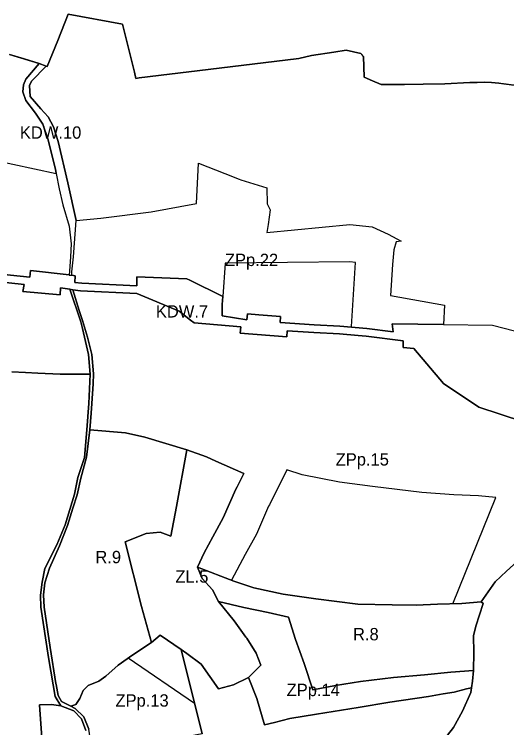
# Model space of a CAD drawing. Extents: x 7418114 to 7422197, y 5546299 to 5548348.
# Drawn here: x 7419820 to 7420219, y 5547025 to 5547603 of the extents above; entities that cross this region are included whole.
import ezdxf

# ---------------------------------------------------------------- set-up
doc = ezdxf.new("R2010")
doc.units = 0
for name, color, linetype in [('_STRZELNICA_SIKORNIK', 7, 'Continuous'), ('linie_lokalizacyjne', 7, 'Continuous'), ('linie_rozgraniczajace', 7, 'Continuous'), ('oznaczenia_przeznaczen', 7, 'Continuous')]:
    doc.layers.add(name, color=color, linetype=linetype)

msp = doc.modelspace()

# ---------------------------------------------------------------- linework, layer by layer
at = {"layer": '_STRZELNICA_SIKORNIK'}
msp.add_lwpolyline([(7419816.43, 5547570.76), (7419840.61, 5547563.53), (7419846.25, 5547561.23), (7419847.04, 5547560.97), (7419855.58, 5547582.15), (7419864.12, 5547603.34), (7419908.13, 5547595.43), (7419917.74, 5547556.32), (7419919, 5547551.22), (7419921.65, 5547551.82), (7419986.34, 5547559.67), (7420051.04, 5547567.5), (7420061.08, 5547569.85), (7420079.37, 5547572.65), (7420089.14, 5547574.3), (7420101.06, 5547571.55), (7420103.3, 5547569.25), (7420103.75, 5547552.48), (7420110.66, 5547549.52), (7420117.58, 5547546.55), (7420136.39, 5547546.49), (7420151.56, 5547546.66), (7420169.15, 5547546.87), (7420189.5, 5547547.96), (7420195.24, 5547548.2), (7420200.99, 5547548.43), (7420206.94, 5547547.99), (7420212.89, 5547547.55), (7420244.04, 5547543.38)], dxfattribs=at)
at = {"layer": 'linie_lokalizacyjne'}
for points in [[(7420093.68, 5547350.47), (7420096.72, 5547402.35), (7420092.13, 5547402.79), (7419991.18, 5547401.81), (7419989.24, 5547374.67)], [(7420041.28, 5547234.25), (7420027.07, 5547205.92), (7420026.39, 5547204.82), (7420016.55, 5547182.22), (7420007.52, 5547165.77), (7419996.33, 5547145)], [(7420210.53, 5547211.94), (7420196.36, 5547213.25), (7420176.4, 5547214.18), (7420150.42, 5547216.04), (7420110.67, 5547220.76), (7420083.74, 5547224.37), (7420053.75, 5547230.19), (7420041.28, 5547234.25)], [(7420175.57, 5547125.84), (7420210.53, 5547211.94)], [(7419966.43, 5547045.05), (7419912.67, 5547081.91)]]:
    msp.add_lwpolyline(points, dxfattribs=at)
at = {"layer": 'linie_rozgraniczajace'}
for p, q in [((7419829.88, 5547550.8), (7419840.61, 5547563.53)), ((7419846.25, 5547561.23), (7419834.32, 5547549.06)), ((7419846.25, 5547561.23), (7419840.61, 5547563.53)), ((7419834.32, 5547549.06), (7419832.71, 5547545.52)), ((7419833.34, 5547536.82), (7419832.71, 5547545.52)), ((7419832.71, 5547545.52), (7419833.34, 5547536.82)), ((7420189.5, 5547547.97), (7420169.16, 5547546.87)), ((7419829.88, 5547533.56), (7419837.5, 5547523.32)), ((7419837.5, 5547523.32), (7419843.5, 5547514.44)), ((7419843.5, 5547514.44), (7419837.5, 5547523.32)), ((7419852.27, 5547512.04), (7419847.76, 5547520.37)), ((7419847.76, 5547520.37), (7419852.27, 5547512.04)), ((7419843.5, 5547514.44), (7419847.48, 5547502.44)), ((7419852.27, 5547512.04), (7419855.88, 5547500.36)), ((7419847.48, 5547502.44), (7419853.74, 5547477.81)), ((7419853.74, 5547477.81), (7419854.38, 5547474.48)), ((7420025.11, 5547462.85), (7420025.2, 5547449.89)), ((7419931.39, 5547443.3), (7419967.97, 5547450.04)), ((7419890.59, 5547438.1), (7419931.39, 5547443.3)), ((7420123.3, 5547425.21), (7420133.69, 5547419.69)), ((7419866.94, 5547394.67), (7419868.47, 5547406.76)), ((7419867.06, 5547391.89), (7419866.94, 5547394.67)), ((7419864.92, 5547392.17), (7419867.06, 5547391.89)), ((7420168.02, 5547352.05), (7420207.92, 5547351.59)), ((7420207.92, 5547351.59), (7420225.74, 5547346.86))]:
    msp.add_line(p, q, dxfattribs=at)
for points in [[(7420101.06, 5547571.55), (7420089.14, 5547574.31), (7420079.37, 5547572.65), (7420061.08, 5547569.85), (7420051.04, 5547567.5), (7419986.34, 5547559.67), (7419921.65, 5547551.82), (7419919, 5547551.22), (7419917.74, 5547556.32), (7419908.13, 5547595.43), (7419864.12, 5547603.34), (7419855.58, 5547582.15), (7419847.04, 5547560.97), (7419846.25, 5547561.23)], [(7419840.61, 5547563.53), (7419828.52, 5547567.15), (7419816.43, 5547570.76)], [(7420101.94, 5547570.64), (7420101.94, 5547570.64), (7420101.06, 5547571.55)], [(7420169.16, 5547546.87), (7420151.56, 5547546.66), (7420136.4, 5547546.49), (7420117.58, 5547546.55), (7420110.66, 5547549.52), (7420103.75, 5547552.48), (7420103.3, 5547569.25), (7420101.94, 5547570.64)], [(7419840.61, 5547563.53), (7419829.88, 5547550.8), (7419827.94, 5547546.18)], [(7419832.71, 5547545.52), (7419834.32, 5547549.06), (7419846.25, 5547561.23)], [(7419837.5, 5547523.32), (7419829.88, 5547533.56), (7419827.33, 5547540.52), (7419827.94, 5547546.18), (7419829.88, 5547550.8)], [(7419827.94, 5547546.18), (7419827.33, 5547540.52), (7419829.88, 5547533.56)], [(7420200.99, 5547548.43), (7420195.24, 5547548.2), (7420189.5, 5547547.97)], [(7420212.89, 5547547.55), (7420206.94, 5547547.99), (7420200.99, 5547548.43)], [(7420244.05, 5547543.38), (7420214.57, 5547547.32), (7420212.89, 5547547.55)], [(7419847.76, 5547520.37), (7419842.02, 5547526.73), (7419833.34, 5547536.82)], [(7419833.34, 5547536.82), (7419842.02, 5547526.73), (7419847.76, 5547520.37)], [(7419854.38, 5547474.48), (7419853.74, 5547477.81), (7419847.48, 5547502.44), (7419843.5, 5547514.44)], [(7419868.47, 5547406.76), (7419870.45, 5547436.17), (7419863.69, 5547466.71), (7419855.88, 5547500.36), (7419852.27, 5547512.04)], [(7419855.88, 5547500.36), (7419863.69, 5547466.71), (7419870.45, 5547436.17), (7419890.59, 5547438.1)], [(7419764.68, 5547480.7), (7419775.06, 5547482.43), (7419785.43, 5547484.16), (7419788.3, 5547482.39), (7419801.45, 5547485.6), (7419854.38, 5547474.48)], [(7419801.45, 5547485.6), (7419854.38, 5547474.48), (7419856.82, 5547461.91), (7419859.76, 5547448.87), (7419864.95, 5547431.58), (7419866.38, 5547417.51), (7419866, 5547406.89), (7419865.05, 5547395.37), (7419864.92, 5547392.17), (7419833.44, 5547395.81), (7419833.13, 5547390.31), (7419804.16, 5547393.43)], [(7419967.97, 5547450.04), (7419969.71, 5547482.67), (7419991.02, 5547474.3), (7420002.49, 5547469.91)], [(7419854.38, 5547474.48), (7419856.82, 5547461.91), (7419859.76, 5547448.87)], [(7420002.49, 5547469.91), (7420004.02, 5547469.3), (7420025.11, 5547462.85)], [(7419859.76, 5547448.87), (7419864.95, 5547431.58), (7419866.38, 5547417.51), (7419866, 5547406.89), (7419865.05, 5547395.37), (7419864.92, 5547392.17)], [(7420025.2, 5547449.89), (7420027.76, 5547444.91), (7420026.1, 5547433.19)], [(7420026.1, 5547433.19), (7420025.03, 5547426.47), (7420092.12, 5547432.93), (7420110.44, 5547431.18), (7420123.3, 5547425.21)], [(7420133.69, 5547419.69), (7420129.72, 5547418.91), (7420127.9, 5547412.57)], [(7420127.9, 5547412.57), (7420126.67, 5547400.63), (7420125.2, 5547375.43), (7420168.82, 5547367.82), (7420168.02, 5547352.05)], [(7419804.16, 5547393.43), (7419833.13, 5547390.31), (7419833.44, 5547395.81), (7419864.92, 5547392.17), (7419864.92, 5547392.11), (7419867.06, 5547391.89), (7419869.85, 5547391.51), (7419869.47, 5547386.04), (7419875.1, 5547385.46), (7419919.77, 5547383.47), (7419919.81, 5547390.72), (7419960.25, 5547389.07), (7419962.56, 5547387.92), (7419989.24, 5547374.67), (7419988.86, 5547368.37), (7419988.94, 5547359.04), (7420008.89, 5547355.95), (7420009.25, 5547360.79), (7420018.57, 5547359.98), (7420035.97, 5547358.45), (7420035.69, 5547353.67), (7420063.33, 5547351.77), (7420084.14, 5547350.79), (7420105.98, 5547348.8), (7420127.27, 5547346.04), (7420126.5, 5547352.48), (7420168.01, 5547352.05), (7420168.02, 5547352.05), (7420207.92, 5547351.59), (7420225.74, 5547346.86)], [(7419803.23, 5547387.27), (7419828.31, 5547384.49), (7419827.49, 5547378.8), (7419857.49, 5547375.99), (7419857.92, 5547381.74), (7419865.45, 5547380.62), (7419874.41, 5547354.15), (7419875.64, 5547348.78), (7419880.59, 5547327.87), (7419881.8, 5547311.97), (7419857.71, 5547311.93), (7419839.5, 5547312.52), (7419829.64, 5547313.07), (7419818.41, 5547313.8)], [(7420232.09, 5547273.57), (7420196.74, 5547285.2), (7420168.03, 5547304.27), (7420143.99, 5547332.64), (7420135.38, 5547333.33), (7420135.54, 5547338.73), (7420105.45, 5547342.64), (7420098.87, 5547343.23), (7420083.73, 5547344.59), (7420063.08, 5547345.58), (7420041.38, 5547346.92), (7420041.22, 5547342.07), (7420003.42, 5547345.18), (7420004.01, 5547350.06), (7419966.27, 5547353.29), (7419963.16, 5547355.71), (7419954.1, 5547362.73), (7419919.75, 5547377.25), (7419874.03, 5547379.35), (7419867.96, 5547380.26), (7419865.45, 5547380.62), (7419857.92, 5547381.74), (7419857.49, 5547375.99), (7419827.49, 5547378.8), (7419828.31, 5547384.49), (7419803.23, 5547387.27)], [(7419878.44, 5547023.2), (7419874.78, 5547032.78), (7419868.77, 5547039.05), (7419858.06, 5547043.25), (7419853.61, 5547050.63), (7419851.83, 5547060.3), (7419848.14, 5547082.36), (7419842, 5547122.98), (7419841.7, 5547132.89), (7419842.9, 5547143.47), (7419845.18, 5547154.46), (7419855, 5547173.59), (7419861.52, 5547189.77), (7419869.14, 5547214.61), (7419872, 5547228.1), (7419877.26, 5547244.27), (7419879.19, 5547266.83), (7419880.94, 5547288.07), (7419881.8, 5547311.97), (7419880.59, 5547327.87), (7419875.64, 5547348.78), (7419874.41, 5547354.15), (7419865.45, 5547380.62), (7419867.96, 5547380.26), (7419872.91, 5547363.49), (7419875.65, 5547355.22), (7419879.79, 5547341.73), (7419883.38, 5547327.88), (7419884.71, 5547312.04), (7419884.25, 5547304.01), (7419883.35, 5547287.95), (7419882.77, 5547280.29), (7419881.76, 5547266.87), (7419878.82, 5547244.56), (7419874.39, 5547227.49), (7419871.35, 5547214.11), (7419867.97, 5547203.43), (7419863.46, 5547189.14), (7419856.94, 5547172.88), (7419848.88, 5547154.81), (7419845.12, 5547142.7), (7419844, 5547133.08), (7419844.67, 5547123.16), (7419849.6, 5547090.42), (7419854.15, 5547061.24), (7419854.27, 5547060.48), (7419855.91, 5547051.6), (7419858.79, 5547046.79), (7419866.28, 5547042.91), (7419866.28, 5547042.91), (7419869.75, 5547041.1), (7419876.89, 5547034.4), (7419880.8, 5547024.17)], [(7420227.67, 5547160.09), (7420219.04, 5547152.14), (7420210, 5547143.69), (7420198.49, 5547127.38), (7420183.08, 5547126.1), (7420163.27, 5547125.41), (7420145.92, 5547124.67), (7420126.47, 5547124.94), (7420098.78, 5547125.64), (7420064.57, 5547129.76), (7420038.25, 5547133.72), (7420014.38, 5547138.83), (7419998.37, 5547144.21), (7419968.76, 5547155.56), (7419974.16, 5547167.09), (7419981.16, 5547180.1), (7419989.6, 5547195.46), (7419999.76, 5547218.81), (7420000.88, 5547220.6), (7420006.29, 5547231.4), (7419983.76, 5547241.5), (7419976.23, 5547244.77), (7419960.13, 5547250.46), (7419926.3, 5547260.93), (7419910.48, 5547264.39), (7419881.76, 5547266.87), (7419882.77, 5547280.29), (7419883.35, 5547287.95), (7419884.25, 5547304.01), (7419884.71, 5547312.04), (7419883.38, 5547327.88), (7419879.79, 5547341.73), (7419875.65, 5547355.22), (7419872.91, 5547363.49), (7419867.96, 5547380.26), (7419874.03, 5547379.35), (7419919.75, 5547377.25), (7419954.1, 5547362.73), (7419963.16, 5547355.71), (7419966.27, 5547353.29), (7420004.01, 5547350.06), (7420003.42, 5547345.18), (7420041.22, 5547342.07), (7420041.38, 5547346.92), (7420063.08, 5547345.58), (7420083.73, 5547344.59), (7420098.87, 5547343.23), (7420105.45, 5547342.64), (7420135.54, 5547338.73), (7420135.38, 5547333.33), (7420143.99, 5547332.64), (7420168.03, 5547304.27), (7420196.74, 5547285.2), (7420232.09, 5547273.57)], [(7419818.41, 5547313.8), (7419829.64, 5547313.07), (7419839.5, 5547312.52), (7419857.71, 5547311.93), (7419881.8, 5547311.97), (7419880.94, 5547288.07), (7419879.19, 5547266.83), (7419877.26, 5547244.27), (7419872, 5547228.1), (7419869.14, 5547214.61), (7419861.52, 5547189.77), (7419855, 5547173.59), (7419845.18, 5547154.46), (7419842.9, 5547143.47), (7419841.7, 5547132.89), (7419842, 5547122.98), (7419848.14, 5547082.36), (7419851.83, 5547060.3), (7419853.61, 5547050.63), (7419858.06, 5547043.25), (7419850.56, 5547044.22), (7419840.83, 5547044.02), (7419844.11, 5546998.05)], [(7420168.31, 5547015.71), (7420176.23, 5547025.58), (7420183.38, 5547038.9), (7420190.11, 5547054.09), (7420190.76, 5547057.84), (7420191.56, 5547063.25), (7420192.51, 5547071.95), (7420192.56, 5547086.52), (7420192.46, 5547099.78), (7420194.25, 5547107.67), (7420200.15, 5547126.13), (7420198.49, 5547127.38), (7420210, 5547143.69), (7420219.04, 5547152.14), (7420227.67, 5547160.09)], [(7419972.53, 5547020.52), (7419955.53, 5547088.89), (7419960.29, 5547085.61), (7419971.7, 5547076.96), (7419985.83, 5547056.98), (7419998.04, 5547060.15), (7420010.14, 5547066.2), (7420016.96, 5547049.09), (7420023.21, 5547027.79), (7420031.19, 5547029.77), (7420043.61, 5547032.85), (7420065.31, 5547036.37), (7420099.09, 5547041.84), (7420124.53, 5547046.04), (7420155.93, 5547050.79), (7420167.71, 5547052.81), (7420176.77, 5547054.36), (7420186.81, 5547056.99), (7420190.76, 5547057.84), (7420190.11, 5547054.09), (7420183.38, 5547038.9), (7420176.23, 5547025.58), (7420168.31, 5547015.71)], [(7419844.11, 5546998.05), (7419840.83, 5547044.02), (7419850.56, 5547044.22), (7419858.06, 5547043.25), (7419868.77, 5547039.05), (7419874.78, 5547032.78), (7419878.44, 5547023.2)]]:
    msp.add_lwpolyline(points, dxfattribs=at)
for points in [[(7419866.94, 5547394.67), (7419868.47, 5547406.76), (7419870.45, 5547436.17), (7419890.59, 5547438.1), (7419931.39, 5547443.3), (7419967.97, 5547450.04), (7419969.71, 5547482.67), (7419991.02, 5547474.3), (7420002.49, 5547469.91), (7420004.02, 5547469.3), (7420025.11, 5547462.85), (7420025.2, 5547449.89), (7420027.76, 5547444.91), (7420026.1, 5547433.19), (7420025.03, 5547426.47), (7420092.12, 5547432.93), (7420110.44, 5547431.18), (7420123.3, 5547425.21), (7420133.69, 5547419.69), (7420129.72, 5547418.91), (7420127.9, 5547412.57), (7420126.67, 5547400.63), (7420125.2, 5547375.43), (7420168.82, 5547367.82), (7420168.02, 5547352.05), (7420168.01, 5547352.05), (7420126.5, 5547352.48), (7420127.27, 5547346.04), (7420105.98, 5547348.8), (7420084.14, 5547350.79), (7420063.33, 5547351.77), (7420035.69, 5547353.67), (7420035.97, 5547358.45), (7420018.57, 5547359.98), (7420009.25, 5547360.79), (7420008.89, 5547355.95), (7419988.94, 5547359.04), (7419988.86, 5547368.37), (7419989.24, 5547374.67), (7419962.56, 5547387.92), (7419960.25, 5547389.07), (7419919.81, 5547390.72), (7419919.77, 5547383.47), (7419875.1, 5547385.46), (7419869.47, 5547386.04), (7419869.85, 5547391.51), (7419867.06, 5547391.89)], [(7419844, 5547133.08), (7419845.12, 5547142.7), (7419848.88, 5547154.81), (7419856.94, 5547172.88), (7419863.46, 5547189.14), (7419867.97, 5547203.43), (7419871.35, 5547214.11), (7419874.39, 5547227.49), (7419878.82, 5547244.56), (7419881.76, 5547266.87), (7419910.48, 5547264.39), (7419926.3, 5547260.93), (7419960.13, 5547250.46), (7419951.81, 5547204.55), (7419947.28, 5547180.67), (7419938.51, 5547183.75), (7419927.22, 5547182.9), (7419910.19, 5547175.98), (7419923.48, 5547123.57), (7419931.62, 5547094.6), (7419916.45, 5547084.56), (7419904.63, 5547076.27), (7419894.5, 5547067.18), (7419888.8, 5547063.06), (7419880.16, 5547059.55), (7419876.24, 5547055.72), (7419873.48, 5547049.14), (7419870.32, 5547044.39), (7419867.1, 5547043.21), (7419866.28, 5547042.91), (7419858.79, 5547046.79), (7419855.91, 5547051.6), (7419854.27, 5547060.48), (7419854.15, 5547061.24), (7419849.6, 5547090.42), (7419844.67, 5547123.16)], [(7419910.19, 5547175.98), (7419927.22, 5547182.9), (7419938.51, 5547183.75), (7419947.28, 5547180.67), (7419951.81, 5547204.55), (7419960.13, 5547250.46), (7419976.23, 5547244.77), (7419983.76, 5547241.5), (7420006.29, 5547231.4), (7420000.88, 5547220.6), (7419999.76, 5547218.81), (7419989.6, 5547195.46), (7419981.16, 5547180.1), (7419974.16, 5547167.09), (7419968.76, 5547155.56), (7419972.54, 5547146.37), (7419980.86, 5547137.28), (7419985.82, 5547127.62), (7419998.59, 5547112.07), (7420008.12, 5547098.89), (7420008.73, 5547097.95), (7420016.46, 5547085.97), (7420020.01, 5547076.03), (7420010.14, 5547066.2), (7419998.04, 5547060.15), (7419985.83, 5547056.98), (7419971.7, 5547076.96), (7419960.29, 5547085.61), (7419955.53, 5547088.89), (7419938.65, 5547100.47), (7419931.62, 5547094.6), (7419923.48, 5547123.57)], [(7419968.76, 5547155.56), (7419998.37, 5547144.21), (7420014.38, 5547138.83), (7420038.25, 5547133.72), (7420064.57, 5547129.76), (7420098.78, 5547125.64), (7420126.47, 5547124.94), (7420145.92, 5547124.67), (7420163.27, 5547125.41), (7420183.08, 5547126.1), (7420198.49, 5547127.38), (7420200.15, 5547126.13), (7420194.25, 5547107.67), (7420192.46, 5547099.78), (7420192.56, 5547086.52), (7420192.51, 5547071.95), (7420174.04, 5547070.42), (7420152.61, 5547068.41), (7420127.49, 5547066.18), (7420100.91, 5547062.98), (7420080.73, 5547059.69), (7420062.22, 5547056.08), (7420055.12, 5547077.46), (7420048.33, 5547096.82), (7420042.44, 5547114.89), (7420026.05, 5547118.73), (7420006.24, 5547122.87), (7419985.82, 5547127.62), (7419980.86, 5547137.28), (7419972.54, 5547146.37)], [(7419985.82, 5547127.62), (7420006.24, 5547122.87), (7420026.05, 5547118.73), (7420042.44, 5547114.89), (7420048.33, 5547096.82), (7420055.12, 5547077.46), (7420062.22, 5547056.08), (7420080.73, 5547059.69), (7420100.91, 5547062.98), (7420127.49, 5547066.18), (7420152.61, 5547068.41), (7420174.04, 5547070.42), (7420192.51, 5547071.95), (7420191.56, 5547063.25), (7420190.76, 5547057.84), (7420186.81, 5547056.99), (7420176.77, 5547054.36), (7420167.71, 5547052.81), (7420155.93, 5547050.79), (7420124.53, 5547046.04), (7420099.09, 5547041.84), (7420065.31, 5547036.37), (7420043.61, 5547032.85), (7420031.19, 5547029.77), (7420023.21, 5547027.79), (7420016.96, 5547049.09), (7420010.14, 5547066.2), (7420020.01, 5547076.03), (7420016.46, 5547085.97), (7420008.73, 5547097.95), (7420008.12, 5547098.89), (7419998.59, 5547112.07)], [(7419866.28, 5547042.91), (7419867.1, 5547043.21), (7419870.32, 5547044.39), (7419873.48, 5547049.14), (7419876.24, 5547055.72), (7419880.16, 5547059.55), (7419888.8, 5547063.06), (7419894.5, 5547067.18), (7419904.63, 5547076.27), (7419916.45, 5547084.56), (7419931.62, 5547094.6), (7419938.65, 5547100.47), (7419955.53, 5547088.89), (7419972.53, 5547020.52), (7419939.92, 5547014.2), (7419922.63, 5547011.63), (7419898.04, 5547008.4), (7419885.91, 5547007.85), (7419883.01, 5547010.34), (7419880.8, 5547024.17), (7419876.89, 5547034.4), (7419869.75, 5547041.1), (7419866.28, 5547042.91)]]:
    msp.add_lwpolyline(points, close=True, dxfattribs=at)

# ---------------------------------------------------------------- texts
at = {"layer": 'oznaczenia_przeznaczen'}
for s, p in [('KDW.10', (7419824.95, 5547502.55)), ('ZPp.22', (7419991.06, 5547399.42)), ('KDW.7', (7419935.12, 5547357.72)), ('ZPp.15', (7420080.76, 5547237.81)), ('R.9', (7419886.13, 5547158.7)), ('ZL.5', (7419950.89, 5547142.96)), ('R.8', (7420094.8, 5547096.25)), ('ZPp.14', (7420041.04, 5547051.08)), ('ZPp.13', (7419902.4, 5547042.54))]:
    msp.add_text(s, height=10, dxfattribs=at).set_placement(p)

doc.saveas('drawing.dxf')
